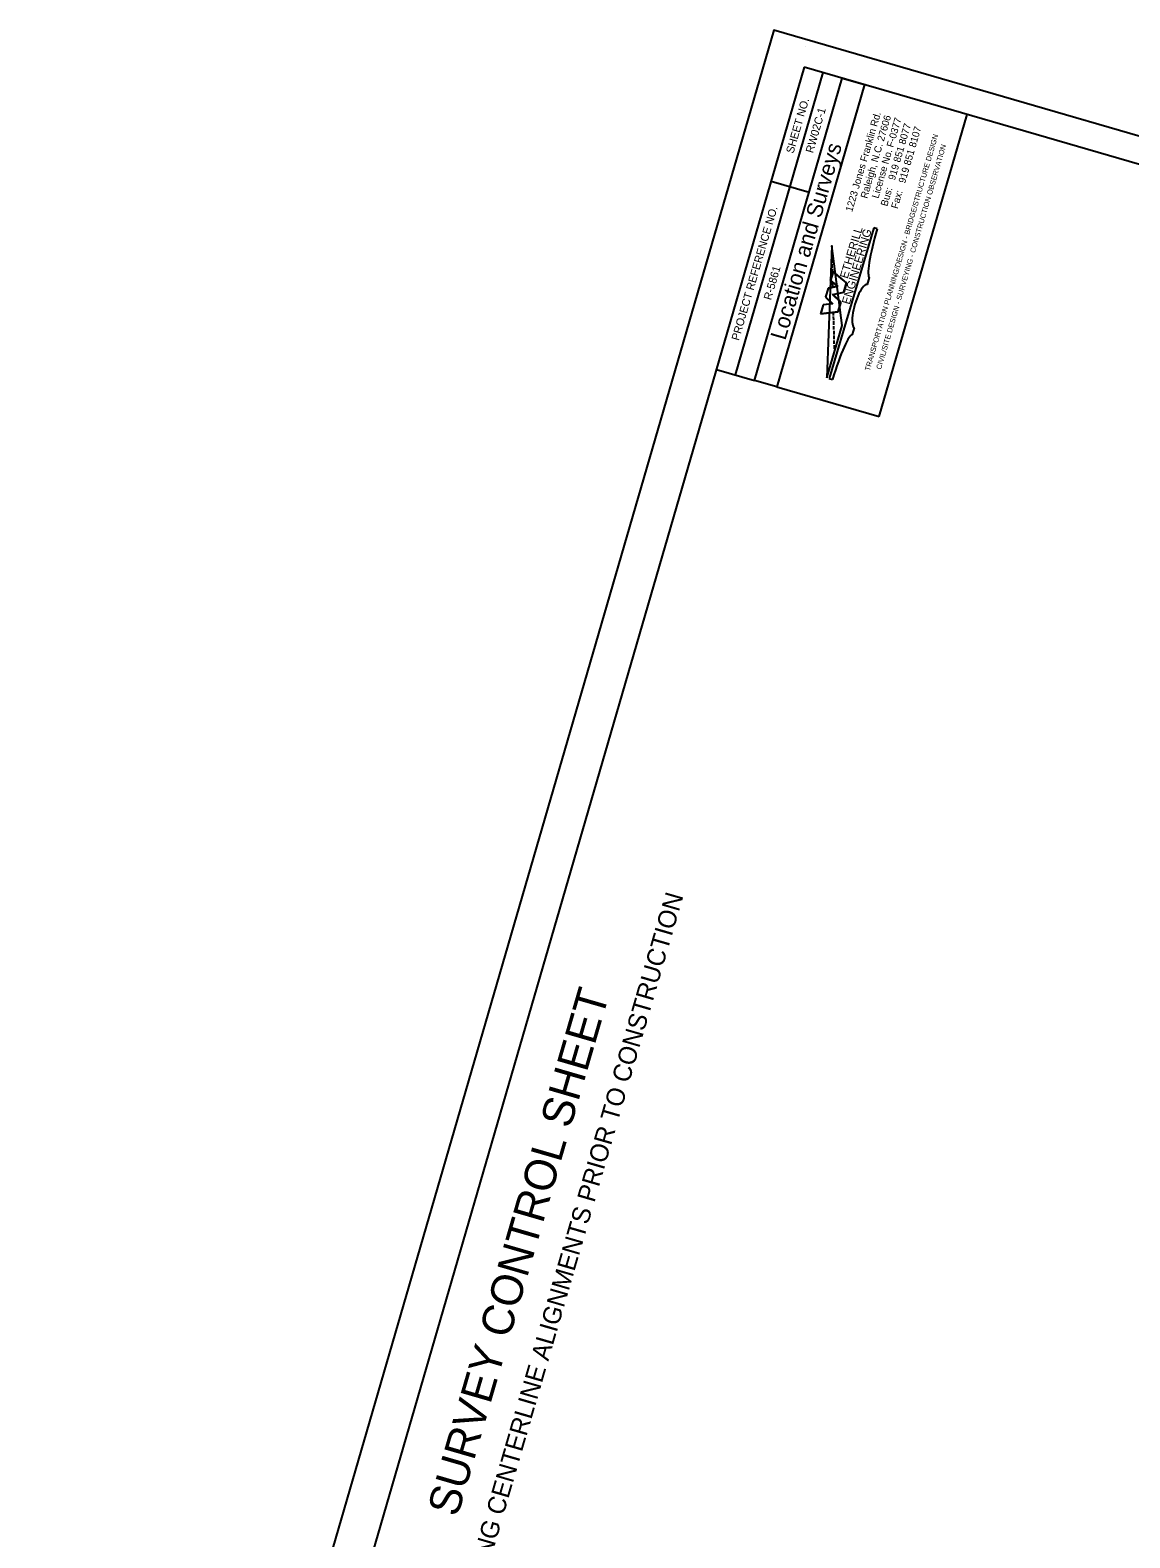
# Model space of a CAD drawing. Extents: x 479429 to 482809, y 488118 to 492379.
# Drawn here: x 479429 to 480968, y 490269 to 492379 of the extents above; entities that cross this region are included whole.
import ezdxf

# ---------------------------------------------------------------- set-up
doc = ezdxf.new("R2010")
doc.units = 0
for name, color, linetype in [('CTL Sheet Border CELL', 7, 'Continuous'), ('CTL Sheet Notes CELL', 7, 'Continuous'), ('Sheet Plot Border Outside CELL', 7, 'Continuous')]:
    doc.layers.add(name, color=color, linetype=linetype)

msp = doc.modelspace()

# ---------------------------------------------------------------- linework, layer by layer
at = {"layer": 'CTL Sheet Border CELL'}
for p, q in [((480469.5, 492378.7), (480469.5, 492378.7)), ((480514.4, 492355.3), (480514.4, 492355.3)), ((480514.4, 492355.3), (480514.4, 492355.3)), ((480416, 491896.3), (480538.8, 492319.4)), ((480617.3, 491837.8), (480740.1, 492260.9)), ((480465.9, 492167.6), (480519.1, 492152.1)), ((480389.4, 491904), (480442.5, 491888.6)), ((480473.8, 491879.5), (480617.3, 491837.8))]:
    msp.add_line(p, q, dxfattribs=at)
for points in [[(480512.1, 492327.1), (479585.7, 489136.9), (481818.8, 488488.4), (482745.3, 491678.6)], [(480442.5, 491888.6), (480565.4, 492311.6), (480596.7, 492302.6), (480473.8, 491879.5)]]:
    msp.add_lwpolyline(points, close=True, dxfattribs=at)
at = {"layer": 'CTL Sheet Notes CELL'}
for p, q in [((480609.5, 492102), (480546.9, 491891.1)), ((480614.3, 492100.6), (480609.5, 492102)), ((480551.2, 492059.6), (480551, 492064.6)), ((480552.5, 492041), (480548.7, 492028.3)), ((480551.3, 492052.9), (480551.2, 492057.9)), ((480551.5, 492046.2), (480551.4, 492051.2)), ((480551.7, 492039.6), (480551.6, 492044.6)), ((480558.6, 492020.2), (480545.5, 492017.6)), ((480559.3, 492020), (480545.8, 492017.3)), ((480548.7, 492028.3), (480558.6, 492020.2)), ((480552.7, 492040.4), (480549.1, 492028.5)), ((480549.1, 492028.5), (480559.3, 492020)), ((480552.2, 492019.6), (480552.1, 492024.6)), ((480571.5, 492024.9), (480552.7, 492040.4)), ((480567.7, 492012.1), (480571.5, 492024.9)), ((480568, 492011.8), (480571.9, 492025)), ((480600.8, 492022.9), (480603.6, 492032.5)), ((480545.5, 492017.6), (480541.8, 492005.2)), ((480541.8, 492005.2), (480551.4, 491995.9)), ((480545.8, 492017.3), (480542.2, 492005.3)), ((480542.2, 492005.3), (480552.1, 491995.6)), ((480552, 492008.9), (480567.7, 492012.1)), ((480563.4, 491997.7), (480552, 492008.9)), ((480552.7, 492008.7), (480568, 492011.8)), ((480563.8, 491997.8), (480552.7, 492008.7)), ((480538.7, 491994.4), (480534.9, 491981.7)), ((480534.9, 491981.7), (480559.9, 491984.6)), ((480538.9, 491994.1), (480535.4, 491982.1)), ((480535.4, 491982.1), (480559.6, 491984.9)), ((480551.4, 491995.9), (480538.7, 491994.4)), ((480552.1, 491995.6), (480538.9, 491994.1)), ((480553.3, 491979.6), (480553.1, 491984.6)), ((480553.5, 491972.9), (480553.3, 491977.9)), ((480559.6, 491984.9), (480563.4, 491997.7)), ((480559.9, 491984.6), (480563.8, 491997.8)), ((480553.6, 491966.3), (480553.5, 491971.3)), ((480553.8, 491959.6), (480553.7, 491964.6)), ((480554, 491952.9), (480553.9, 491957.9)), ((480579.9, 491952.6), (480582.8, 491962.2)), ((480554.2, 491946.3), (480554, 491951.3)), ((480554.3, 491939.6), (480554.2, 491944.6)), ((480554.5, 491932.9), (480554.4, 491937.9)), ((480546.9, 491891.1), (480551.7, 491889.7))]:
    msp.add_line(p, q, dxfattribs=at)
msp.add_lwpolyline([(480543.7, 491892), (480565.5, 491965.5), (480550.7, 492077.1)], close=True, dxfattribs=at)
msp.add_lwpolyline([(480571.9, 492025), (480571.6, 492025.2), (480552.5, 492041)], dxfattribs=at)
for centre, major_axis, ratio, start_param, end_param in [((480623.1, 492098), (19.4, 65.5), 0.134146, 1.570796, 3.141593), ((480591.8, 491992.5), (9, 30.4), 0.289474, 0, 3.141593), ((480560.5, 491887.1), (-19.4, -65.5), 0.134146, 3.141593, 4.712389)]:
    msp.add_ellipse(centre, major_axis=major_axis, ratio=ratio, start_param=start_param, end_param=end_param, dxfattribs=at)
at = {"layer": 'Sheet Plot Border Outside CELL'}
msp.add_lwpolyline([(481768.9, 488117.8), (482808.9, 491699.3), (480469.5, 492378.7), (479429.4, 488797.2)], close=True, dxfattribs=at)

# ---------------------------------------------------------------- texts
at = {"layer": 'CTL Sheet Border CELL'}
for s, height, p in [('SHEET NO.', 11.07, (480497.1, 492205.4)), ('RW02C-1', 11.07, (480524.5, 492205.9)), ('Location and Surveys', 22.147, (480485.8, 491943.7)), ('PROJECT REFERENCE NO.', 11.074, (480420.8, 491943.5)), ('R-5861', 11.07, (480465.8, 492000.2)), ('W/  EXISTING CENTERLINE ALIGNMENTS PRIOR TO CONSTRUCTION', 25.469, (480027.5, 490079)), ('SURVEY CONTROL SHEET ', 44.294, (480027.1, 490296.5))]:
    msp.add_text(s, height=height, rotation=73.8071, dxfattribs=at).set_placement(p)
at = {"layer": 'CTL Sheet Notes CELL'}
for s, height, rotation, p in [('1223 Jones Franklin Rd. ', 10, 73.8069, (480579.3, 492123.7)), ('Raleigh, N.C. 27606', 10, 73.8069, (480600.3, 492142.4)), ('License No. F-0377', 10, 73.8069, (480616, 492142.5)), ('Bus:   919 851 8077', 10, 73.8069, (480628.4, 492131.5)), ('Fax:   919 851 8107', 10, 73.8069, (480643, 492128)), ('TRANSPORTATION PLANNING/DESIGN - BRIDGE/STRUCTURE DESIGN', 7.333, 73.8069, (480603.8, 491901.2)), ('CIVIL/SITE DESIGN - SURVEYING - CONSTRUCTION OBSERVATION', 7.333, 73.8069, (480619.7, 491903.2)), ('ETHERILL', 11.67, 73.4805, (480573, 492030.2)), ('ENGINEERING', 11.667, 73.4805, (480575.7, 491994))]:
    msp.add_text(s, height=height, rotation=rotation, dxfattribs=at).set_placement(p)

doc.saveas('drawing.dxf')
